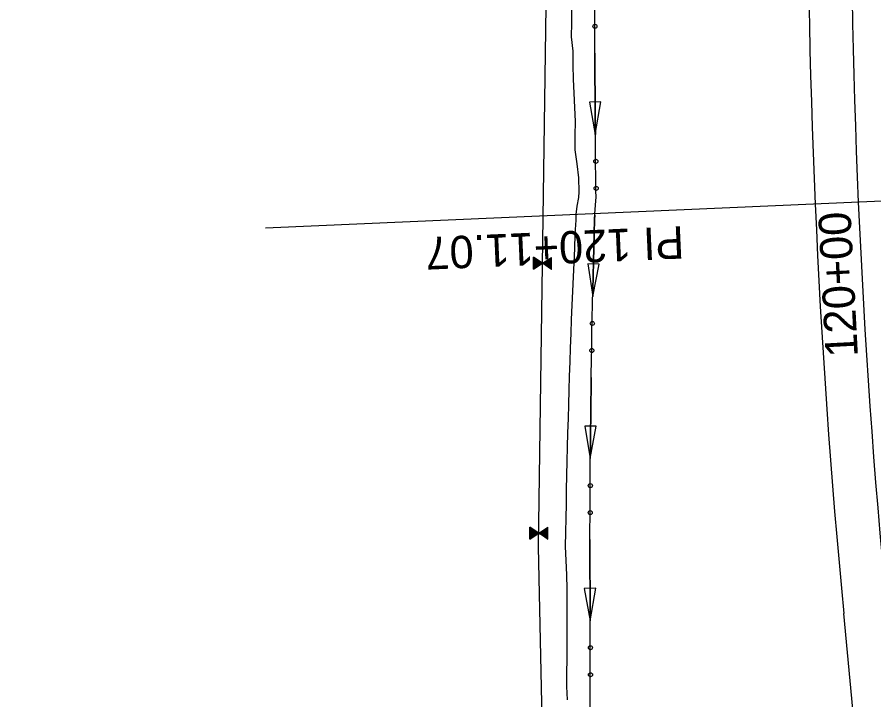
# Model space of a CAD drawing. Extents: x 1311167 to 1314552, y 2087587 to 2090602.
# Drawn here: x 1313838.8 to 1313997.5, y 2089912.8 to 2090039.3 of the extents above; entities that cross this region are included whole.
import ezdxf

# ---------------------------------------------------------------- set-up
doc = ezdxf.new("R2010")
doc.units = 0
for name, color, linetype in [('R_Bridge', 7, 'Continuous'), ('R_Guardrail', 7, 'Continuous'), ('R_Horz Alg Stationing', 7, 'Continuous'), ('R_Proposed Road', 7, 'Continuous'), ('S_DITCHLINE', 7, 'Continuous'), ('S_DROP_INLET', 7, 'Continuous'), ('S_EDGE_CONCRETE', 7, 'Continuous'), ('S_EDGE_PAVEMENT', 7, 'Continuous'), ('S_PAVEMENT_CROWN', 7, 'Continuous')]:
    doc.layers.add(name, color=color, linetype=linetype)

msp = doc.modelspace()

# ---------------------------------------------------------------- linework, layer by layer
at = {"layer": 'R_Guardrail'}
msp.add_lwpolyline([(1314004.67, 2090005.41), (1313884.79, 2090000.17)], dxfattribs=at)
at = {"layer": 'R_Horz Alg Stationing'}
msp.add_arc((1313903.45, 2090013.7), 190.97, 89.1292, 178.95, dxfattribs=at)
at = {"layer": 'R_Proposed Road'}
msp.add_arc((1313906.1, 2090010.65), 201.04, 89.25, 178.95, dxfattribs=at)
msp.add_arc((1313906.1, 2090010.65), 201.04, 89.25, 178.95, dxfattribs=at)
at = {"layer": 'S_DITCHLINE'}
for p, q in [((1313946.93, 2090023.55), (1313944.82, 2090023.53)), ((1313946.93, 2090023.55), (1313944.82, 2090023.53)), ((1313944.82, 2090023.53), (1313945.92, 2090017.54)), ((1313944.82, 2090023.53), (1313945.92, 2090017.54)), ((1313945.92, 2090017.54), (1313946.93, 2090023.55)), ((1313945.92, 2090017.54), (1313946.93, 2090023.55)), ((1313946.63, 2089993.49), (1313944.51, 2089993.54)), ((1313944.51, 2089993.54), (1313945.44, 2089987.52)), ((1313946.63, 2089993.49), (1313944.51, 2089993.54)), ((1313944.51, 2089993.54), (1313945.44, 2089987.52)), ((1313945.44, 2089987.52), (1313946.63, 2089993.49)), ((1313945.44, 2089987.52), (1313946.63, 2089993.49)), ((1313946.11, 2089963.47), (1313944, 2089963.49)), ((1313944, 2089963.49), (1313945, 2089957.48)), ((1313946.11, 2089963.47), (1313944, 2089963.49)), ((1313944, 2089963.49), (1313945, 2089957.48)), ((1313945, 2089957.48), (1313946.11, 2089963.47)), ((1313945, 2089957.48), (1313946.11, 2089963.47)), ((1313945.99, 2089933.45), (1313943.88, 2089933.44)), ((1313945.99, 2089933.45), (1313943.88, 2089933.44)), ((1313943.88, 2089933.44), (1313944.96, 2089927.45)), ((1313943.88, 2089933.44), (1313944.96, 2089927.45)), ((1313944.96, 2089927.45), (1313945.99, 2089933.45)), ((1313944.96, 2089927.45), (1313945.99, 2089933.45))]:
    msp.add_line(p, q, dxfattribs=at)
for points in [[(1313945, 2089910.68), (1313945, 2089913.19), (1313945, 2089915.7), (1313944.99, 2089918.21), (1313944.99, 2089920.72), (1313944.98, 2089923.24), (1313944.97, 2089925.82), (1313944.96, 2089928.44), (1313944.95, 2089931.07), (1313944.94, 2089933.7), (1313944.93, 2089936.32), (1313944.93, 2089938.95), (1313944.93, 2089941.57), (1313944.93, 2089944.19), (1313944.94, 2089946.82), (1313944.95, 2089949.44), (1313944.96, 2089952.06), (1313944.98, 2089954.69), (1313945, 2089957.31), (1313945.02, 2089959.93), (1313945.05, 2089962.55), (1313945.07, 2089965.17), (1313945.11, 2089967.79), (1313945.14, 2089970.41), (1313945.18, 2089973.02), (1313945.22, 2089975.64), (1313945.26, 2089978.26), (1313945.31, 2089980.87), (1313945.36, 2089983.49), (1313945.41, 2089986.11), (1313945.46, 2089988.72), (1313945.52, 2089991.34), (1313945.59, 2089993.95), (1313945.65, 2089996.56), (1313945.72, 2089999.18), (1313945.79, 2090001.79), (1313945.82, 2090002.84), (1313945.94, 2090004.4), (1313946.07, 2090005.97), (1313946.05, 2090007.02), (1313946.02, 2090009.62), (1313945.98, 2090012.23), (1313945.96, 2090014.83), (1313945.93, 2090017.44), (1313945.9, 2090020.05), (1313945.88, 2090022.65), (1313945.87, 2090025.26), (1313945.85, 2090027.86), (1313945.84, 2090030.47), (1313945.83, 2090033.07), (1313945.83, 2090035.68), (1313945.82, 2090038.28), (1313945.82, 2090040.89)], [(1313945.83, 2090032.58), (1313945.83, 2090032.54)], [(1313945.83, 2090032.58), (1313945.83, 2090032.54)], [(1313945.83, 2090032.54), (1313945.84, 2090030.47), (1313945.85, 2090027.86), (1313945.87, 2090025.26), (1313945.88, 2090022.65), (1313945.9, 2090020.05), (1313945.93, 2090017.54)], [(1313945.83, 2090032.54), (1313945.84, 2090030.47), (1313945.85, 2090027.86), (1313945.87, 2090025.26), (1313945.88, 2090022.65), (1313945.9, 2090020.05), (1313945.93, 2090017.54)], [(1313945.81, 2090002.51), (1313945.79, 2090001.79), (1313945.72, 2089999.18), (1313945.65, 2089996.56), (1313945.59, 2089993.95), (1313945.52, 2089991.34), (1313945.46, 2089988.72), (1313945.44, 2089987.52)], [(1313945.81, 2090002.51), (1313945.79, 2090001.79), (1313945.72, 2089999.18), (1313945.65, 2089996.56), (1313945.59, 2089993.95), (1313945.52, 2089991.34), (1313945.46, 2089988.72), (1313945.44, 2089987.52)], [(1313945.81, 2090002.55), (1313945.81, 2090002.52)], [(1313945.81, 2090002.55), (1313945.81, 2090002.52)], [(1313945.17, 2089972.48), (1313945.14, 2089970.41), (1313945.11, 2089967.79), (1313945.07, 2089965.17), (1313945.05, 2089962.55), (1313945.02, 2089959.93), (1313945, 2089957.48)], [(1313945.17, 2089972.48), (1313945.14, 2089970.41), (1313945.11, 2089967.79), (1313945.07, 2089965.17), (1313945.05, 2089962.55), (1313945.02, 2089959.93), (1313945, 2089957.48)], [(1313945.17, 2089972.52), (1313945.17, 2089972.48)], [(1313945.17, 2089972.52), (1313945.17, 2089972.48)], [(1313944.93, 2089942.49), (1313944.93, 2089942.45)], [(1313944.93, 2089942.49), (1313944.93, 2089942.45)], [(1313944.93, 2089942.45), (1313944.93, 2089941.57), (1313944.93, 2089938.95), (1313944.93, 2089936.32), (1313944.94, 2089933.7), (1313944.95, 2089931.07), (1313944.96, 2089928.44), (1313944.96, 2089927.45)], [(1313944.93, 2089942.45), (1313944.93, 2089941.57), (1313944.93, 2089938.95), (1313944.93, 2089936.32), (1313944.94, 2089933.7), (1313944.95, 2089931.07), (1313944.96, 2089928.44), (1313944.96, 2089927.45)]]:
    msp.add_lwpolyline(points, dxfattribs=at)
for centre in [(1313945.86, 2090037.56), (1313945.86, 2090037.56), (1313946.02, 2090012.54), (1313946.02, 2090012.54), (1313946.08, 2090007.53), (1313946.08, 2090007.53), (1313945.37, 2089982.51), (1313945.37, 2089982.51), (1313945.28, 2089977.5), (1313945.28, 2089977.5), (1313945, 2089952.48), (1313945, 2089952.48), (1313944.98, 2089947.47), (1313944.98, 2089947.47), (1313945.02, 2089922.44), (1313945.02, 2089922.44), (1313945.03, 2089917.43), (1313945.03, 2089917.43)]:
    msp.add_circle(centre, 0.375, dxfattribs=at)
at = {"layer": 'S_DROP_INLET'}
for p, q in [((1313935.5, 2089993.25), (1313934.48, 2089993.95)), ((1313935.99, 2089993.59), (1313934.49, 2089994.62)), ((1313935.9, 2089993.51), (1313934.49, 2089994.48)), ((1313935.79, 2089993.45), (1313934.49, 2089994.35)), ((1313935.7, 2089993.38), (1313934.49, 2089994.22)), ((1313935.58, 2089993.33), (1313934.49, 2089994.08)), ((1313936.15, 2089993.66), (1313934.5, 2089994.79)), ((1313936.11, 2089993.64), (1313934.5, 2089994.75)), ((1313936.15, 2089993.66), (1313937.83, 2089994.75)), ((1313936.19, 2089993.64), (1313937.83, 2089994.7)), ((1313936.31, 2089993.59), (1313937.83, 2089994.57)), ((1313936.39, 2089993.51), (1313937.82, 2089994.44)), ((1313936.49, 2089993.44), (1313937.82, 2089994.3)), ((1313936.58, 2089993.37), (1313937.82, 2089994.17)), ((1313936.7, 2089993.31), (1313937.82, 2089994.04)), ((1313936.78, 2089993.23), (1313937.82, 2089993.9)), ((1313934.47, 2089992.57), (1313936.15, 2089993.66)), ((1313934.89, 2089992.86), (1313934.47, 2089993.15)), ((1313934.79, 2089992.8), (1313934.47, 2089993.02)), ((1313934.69, 2089992.73), (1313934.47, 2089992.88)), ((1313934.58, 2089992.67), (1313934.47, 2089992.75)), ((1313934.49, 2089992.6), (1313934.47, 2089992.61)), ((1313935.38, 2089993.2), (1313934.48, 2089993.82)), ((1313935.29, 2089993.13), (1313934.48, 2089993.68)), ((1313935.1, 2089992.99), (1313934.48, 2089993.42)), ((1313935, 2089992.92), (1313934.48, 2089993.28)), ((1313935.17, 2089993.08), (1313934.54, 2089993.51)), ((1313937.8, 2089992.53), (1313936.15, 2089993.66)), ((1313936.9, 2089993.18), (1313937.82, 2089993.77)), ((1313936.99, 2089993.1), (1313937.81, 2089993.64)), ((1313937.11, 2089993.05), (1313937.75, 2089993.46)), ((1313937.18, 2089992.96), (1313937.81, 2089993.37)), ((1313937.27, 2089992.89), (1313937.81, 2089993.24)), ((1313937.38, 2089992.83), (1313937.81, 2089993.1)), ((1313937.48, 2089992.76), (1313937.8, 2089992.97)), ((1313937.58, 2089992.69), (1313937.8, 2089992.84)), ((1313937.68, 2089992.63), (1313937.8, 2089992.7)), ((1313937.77, 2089992.55), (1313937.8, 2089992.57)), ((1313935.3, 2089943.6), (1313933.8, 2089944.62)), ((1313935.46, 2089943.67), (1313933.81, 2089944.8)), ((1313935.42, 2089943.65), (1313933.81, 2089944.76)), ((1313935.46, 2089943.67), (1313937.14, 2089944.75)), ((1313935.5, 2089943.65), (1313937.14, 2089944.71)), ((1313933.78, 2089942.58), (1313935.46, 2089943.67)), ((1313934.2, 2089942.86), (1313933.78, 2089943.15)), ((1313934.81, 2089943.26), (1313933.79, 2089943.95)), ((1313934.69, 2089943.2), (1313933.79, 2089943.82)), ((1313934.6, 2089943.13), (1313933.79, 2089943.69)), ((1313934.41, 2089943), (1313933.79, 2089943.42)), ((1313934.31, 2089942.92), (1313933.79, 2089943.29)), ((1313935.21, 2089943.52), (1313933.8, 2089944.49)), ((1313935.1, 2089943.46), (1313933.8, 2089944.35)), ((1313935.01, 2089943.39), (1313933.8, 2089944.22)), ((1313934.89, 2089943.33), (1313933.8, 2089944.09)), ((1313934.48, 2089943.08), (1313933.85, 2089943.51)), ((1313937.11, 2089942.53), (1313935.46, 2089943.67)), ((1313935.62, 2089943.59), (1313937.14, 2089944.58)), ((1313935.7, 2089943.51), (1313937.13, 2089944.44)), ((1313935.8, 2089943.45), (1313937.13, 2089944.31)), ((1313935.89, 2089943.38), (1313937.13, 2089944.18)), ((1313936.01, 2089943.32), (1313937.13, 2089944.04)), ((1313936.09, 2089943.24), (1313937.13, 2089943.91)), ((1313936.21, 2089943.18), (1313937.13, 2089943.78)), ((1313936.3, 2089943.11), (1313937.12, 2089943.64)), ((1313936.42, 2089943.05), (1313937.06, 2089943.47)), ((1313936.49, 2089942.97), (1313937.12, 2089943.37)), ((1313936.58, 2089942.89), (1313937.12, 2089943.24)), ((1313936.69, 2089942.83), (1313937.12, 2089943.11)), ((1313934.1, 2089942.8), (1313933.78, 2089943.02)), ((1313934, 2089942.73), (1313933.78, 2089942.89)), ((1313933.89, 2089942.67), (1313933.78, 2089942.75)), ((1313933.8, 2089942.6), (1313933.78, 2089942.62)), ((1313936.79, 2089942.77), (1313937.11, 2089942.97)), ((1313936.89, 2089942.69), (1313937.11, 2089942.84)), ((1313936.99, 2089942.63), (1313937.11, 2089942.71)), ((1313937.08, 2089942.56), (1313937.11, 2089942.57))]:
    msp.add_line(p, q, dxfattribs=at)
for points in [[(1313938.24, 2089808.01), (1313935.42, 2089941.12), (1313937.11, 2090063.1), (1313957.22, 2090154.8)], [(1313934.47, 2089992.57), (1313934.5, 2089994.79)], [(1313937.8, 2089992.53), (1313937.83, 2089994.75)], [(1313933.78, 2089942.58), (1313933.81, 2089944.8)], [(1313937.11, 2089942.53), (1313937.14, 2089944.75)]]:
    msp.add_lwpolyline(points, dxfattribs=at)
at = {"layer": 'S_EDGE_CONCRETE'}
msp.add_lwpolyline([(1313940.74, 2089912.78), (1313940.66, 2089915.28), (1313940.67, 2089917.8), (1313940.69, 2089920.31), (1313940.7, 2089922.82), (1313940.71, 2089925.41), (1313940.71, 2089928.05), (1313940.72, 2089930.68), (1313940.73, 2089933.32), (1313940.66, 2089935.94), (1313940.54, 2089938.57), (1313940.42, 2089941.19), (1313940.47, 2089943.82), (1313940.51, 2089946.46), (1313940.56, 2089949.09), (1313940.6, 2089951.72), (1313940.66, 2089954.36), (1313940.71, 2089956.99), (1313940.79, 2089959.62), (1313940.86, 2089962.25), (1313940.93, 2089964.88), (1313941.01, 2089967.51), (1313941.08, 2089970.14), (1313941.16, 2089972.77), (1313941.25, 2089975.4), (1313941.34, 2089978.02), (1313941.43, 2089980.65), (1313941.53, 2089983.27), (1313941.63, 2089985.9), (1313941.74, 2089988.52), (1313941.87, 2089991.15), (1313941.98, 2089993.77), (1313942.1, 2089996.39), (1313942.22, 2089999.02), (1313942.35, 2090001.64), (1313942.4, 2090002.69), (1313942.58, 2090004.26), (1313942.86, 2090005.84), (1313942.93, 2090006.89), (1313942.89, 2090009.5), (1313942.55, 2090012.1), (1313942.22, 2090014.7), (1313942.21, 2090017.31), (1313942.27, 2090019.93), (1313942.16, 2090022.54), (1313942.01, 2090025.15), (1313941.87, 2090027.76), (1313941.84, 2090030.37), (1313941.81, 2090032.98), (1313941.52, 2090035.58), (1313941.57, 2090038.2), (1313941.57, 2090040.81)], dxfattribs=at)
at = {"layer": 'S_EDGE_PAVEMENT'}
msp.add_line((1314035.66, 2089474.91), (1313991.96, 2089928.77), dxfattribs=at)
msp.add_arc((1315437.67, 2090067.97), 1452.39, 179.5, 185.5, dxfattribs=at)
at = {"layer": 'S_PAVEMENT_CROWN'}
msp.add_arc((1315437.67, 2090067.97), 1444.39, 179.5, 185.5, dxfattribs=at)

# ---------------------------------------------------------------- texts
at = {"layer": 'R_Bridge'}
msp.add_text('120+00', height=6, rotation=92.9402, dxfattribs=at).set_placement((1313994.59, 2089976.39))
at = {"layer": 'R_Guardrail'}
msp.add_text('PI 120+11.07', height=6, rotation=182.5, dxfattribs=at).set_placement((1313962.24, 2090000.55))

doc.saveas('drawing.dxf')
